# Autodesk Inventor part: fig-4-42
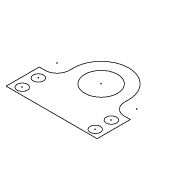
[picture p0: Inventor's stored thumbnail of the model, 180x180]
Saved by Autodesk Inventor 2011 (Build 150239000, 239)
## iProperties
Created: 2004-05
Part Number: fig-4-42
Document SubType Name: Modeling
Designer: CADCIM Technologies
Manufacturer: Standard
Standards Organization: Custom
Density: 1 g/cm^3
Author: CADCIM Technologies
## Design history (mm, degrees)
sketch "Sketch1"
  geometry: L1 (41.331, 50.432)-(41.331, 48.38); L2 (35.331, 42.38)-(32.489, 42.38); L3 (32.489, 42.38)-(32.489, 26.047); L4 (68.481, 50.432)-(68.481, 48.38); L5 (74.481, 42.38)-(77.323, 42.38); L6 (77.323, 42.38)-(77.323, 26.047); L7 (32.489, 26.047)-(77.323, 26.047); C1 r 8.09 at (54.906, 50.432); C2 r 2.534 at (36.931, 29.558); C3 r 2.534 at (36.931, 37.474); C4 r 2.534 at (72.881, 37.474); C5 r 2.534 at (72.881, 29.558); A1 r 13.575 centre (54.906, 50.432) between (68.481, 50.432) and (41.331, 50.432); A2 r 6 centre (35.331, 48.38) between (35.331, 42.38) and (41.331, 48.38); A3 r 6 centre (74.481, 48.38) between (68.481, 48.38) and (74.481, 42.38)
  constraints: 14 end point, 8 centre point, 6 point on circle, 6 tangent, 3 equal length, 2 horizontal, 2 perpendicular, 1 coincident, 1 equal radius, 1 parallel, 1 vertical
